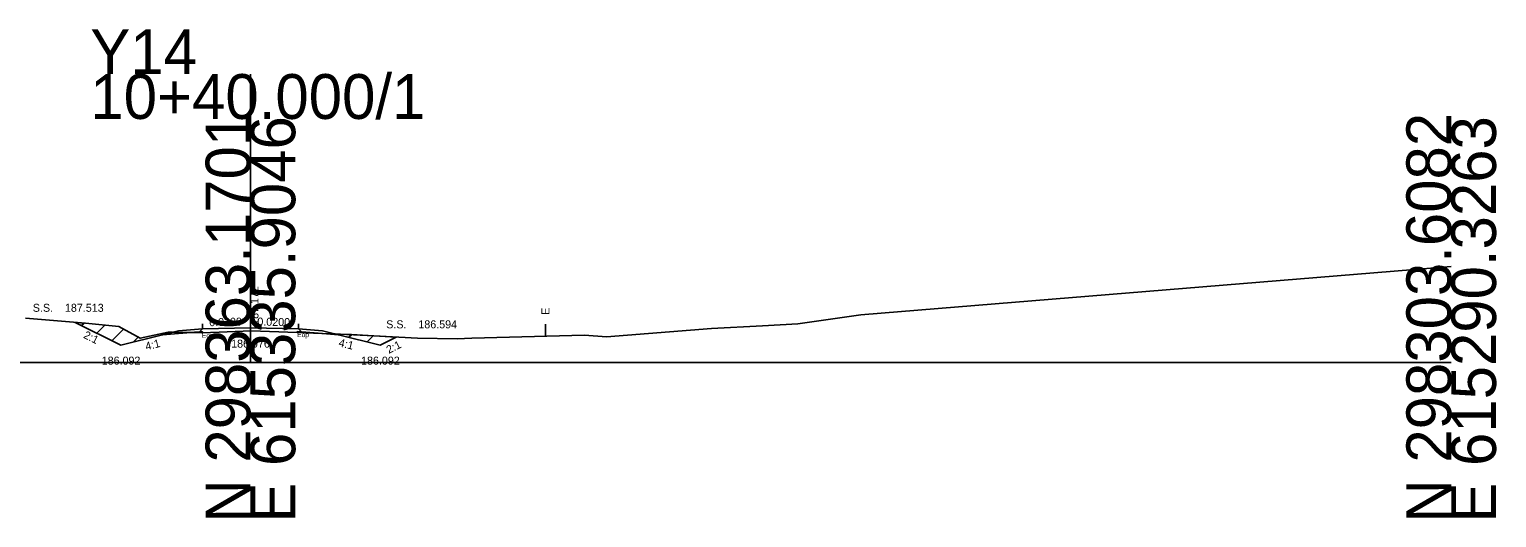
# Model space of a CAD drawing. Extents: x 517327 to 517505, y 114839 to 117370.
# Drawn here: x 517413.6 to 517505.2, y 115838.7 to 115869.2 of the extents above; entities that cross this region are included whole.
import ezdxf

# ---------------------------------------------------------------- set-up
doc = ezdxf.new("R2010")
doc.units = 0
for name, color, linetype in [('Exist XS Ground Line', 7, 'Continuous'), ('Old_Level_60', 7, 'Continuous'), ('Old_Level_63', 7, 'Continuous'), ('Prop XS Dump Level', 7, 'Continuous'), ('Prop XS Earthwork Shape', 7, 'Continuous'), ('Prop XS Elevation Labels', 7, 'Continuous'), ('Prop XS EOT Tick Mark', 7, 'Continuous'), ('Prop XS Exc Vertical Line 1', 7, 'Continuous'), ('Prop XS Finish Grade', 7, 'Continuous'), ('Prop XS Finish Grade Earthwork', 7, 'Continuous'), ('Prop XS Finish Grade Pavement', 7, 'Continuous'), ('Prop XS Hydro Elevations', 7, 'Continuous'), ('Prop XS Label Text', 7, 'Continuous'), ('Prop XS Pvmt Edge Slope', 7, 'Continuous'), ('Prop XS SE Text', 7, 'Continuous'), ('Prop XS Side Slope Text', 7, 'Continuous'), ('Prop XS Subgrade Earthwork', 7, 'Continuous'), ('Prop XS Suitable Common Exc Shape', 7, 'Continuous'), ('Scratch_Level_0', 7, 'Continuous')]:
    doc.layers.add(name, color=color, linetype=linetype)

msp = doc.modelspace()

# ---------------------------------------------------------------- linework, layer by layer
at = {"layer": 'Exist XS Ground Line'}
for p, q in [((517465.493, 115851.36), (517502.365, 115854.375)), ((517413.306, 115851.146), (517417.054, 115850.824)), ((517417.054, 115850.824), (517419.152, 115850.615)), ((517456.159, 115850.488), (517459.355, 115850.658)), ((517459.355, 115850.658), (517461.563, 115850.785)), ((517461.563, 115850.785), (517465.493, 115851.36)), ((517419.152, 115850.615), (517420.485, 115849.887)), ((517420.485, 115849.887), (517422.22, 115850.263)), ((517422.22, 115850.263), (517423.777, 115850.24)), ((517423.777, 115850.24), (517424.332, 115850.22)), ((517424.332, 115850.22), (517425.406, 115850.263)), ((517425.406, 115850.263), (517427.409, 115850.342)), ((517427.409, 115850.342), (517430.285, 115850.255)), ((517430.285, 115850.255), (517433.361, 115850.126)), ((517433.361, 115850.126), (517433.684, 115850.114)), ((517433.684, 115850.114), (517435.073, 115850.038)), ((517435.073, 115850.038), (517437.806, 115849.884)), ((517437.806, 115849.884), (517440.267, 115849.858)), ((517440.267, 115849.858), (517441.2, 115849.891)), ((517441.2, 115849.891), (517448.233, 115850.074)), ((517448.233, 115850.074), (517449.611, 115849.984)), ((517449.611, 115849.984), (517456.159, 115850.488))]:
    msp.add_line(p, q, dxfattribs=at)
at = {"layer": 'Old_Level_63'}
for p, q in [((517427.365, 115848.365), (517427.365, 115866.395)), ((517352.365, 115848.365), (517427.365, 115848.365)), ((517427.365, 115848.365), (517502.365, 115848.365))]:
    msp.add_line(p, q, dxfattribs=at)
at = {"layer": 'Prop XS Dump Level'}
for p, q in [((517424.365, 115850.477), (517427.365, 115850.537)), ((517427.365, 115850.537), (517430.365, 115850.477))]:
    msp.add_line(p, q, dxfattribs=at)
at = {"layer": 'Prop XS Earthwork Shape'}
for points in [[(517416.422, 115850.878), (517417.054, 115850.824), (517419.152, 115850.615), (517420.485, 115849.887), (517422.22, 115850.263), (517423.557, 115850.243), (517422.865, 115850.188), (517421.871, 115850.108), (517419.265, 115849.457)], [(517423.557, 115850.243), (517423.777, 115850.24), (517424.332, 115850.22), (517424.367, 115850.221), (517424.365, 115850.297), (517424.181, 115850.293)], [(517430.285, 115850.298), (517430.283, 115850.255), (517431.832, 115850.19), (517430.549, 115850.293), (517430.365, 115850.297)], [(517431.832, 115850.19), (517433.361, 115850.126), (517433.684, 115850.114), (517435.073, 115850.038), (517436.47, 115849.959), (517435.465, 115849.457), (517432.859, 115850.108), (517431.865, 115850.188)]]:
    msp.add_lwpolyline(points, close=True, dxfattribs=at)
at = {"layer": 'Prop XS EOT Tick Mark'}
for p, q in [((517424.365, 115850.782), (517424.365, 115850.477)), ((517430.365, 115850.477), (517430.365, 115850.782))]:
    msp.add_line(p, q, dxfattribs=at)
at = {"layer": 'Prop XS Exc Vertical Line 1'}
msp.add_line((517445.787, 115850.76), (517445.787, 115850.01), dxfattribs=at)
at = {"layer": 'Prop XS Finish Grade'}
for p, q in [((517421.871, 115850.108), (517422.865, 115850.357)), ((517422.865, 115850.357), (517424.365, 115850.477)), ((517430.365, 115850.477), (517431.865, 115850.357)), ((517431.865, 115850.357), (517432.859, 115850.108))]:
    msp.add_line(p, q, dxfattribs=at)
at = {"layer": 'Prop XS Finish Grade Earthwork'}
for p, q in [((517416.422, 115850.878), (517419.265, 115849.457)), ((517419.265, 115849.457), (517421.871, 115850.108)), ((517432.859, 115850.108), (517435.465, 115849.457)), ((517435.465, 115849.457), (517436.47, 115849.959))]:
    msp.add_line(p, q, dxfattribs=at)
at = {"layer": 'Prop XS Finish Grade Pavement'}
for p, q in [((517427.365, 115850.537), (517424.365, 115850.477)), ((517430.365, 115850.477), (517427.365, 115850.537))]:
    msp.add_line(p, q, dxfattribs=at)
at = {"layer": 'Prop XS Pvmt Edge Slope'}
for p, q in [((517424.181, 115850.293), (517424.365, 115850.477)), ((517430.365, 115850.477), (517430.549, 115850.293))]:
    msp.add_line(p, q, dxfattribs=at)
at = {"layer": 'Prop XS Subgrade Earthwork'}
for p, q in [((517421.871, 115850.108), (517422.865, 115850.188)), ((517422.865, 115850.188), (517424.181, 115850.293)), ((517424.181, 115850.293), (517424.365, 115850.297)), ((517424.367, 115850.221), (517424.365, 115850.297)), ((517430.285, 115850.298), (517430.283, 115850.255)), ((517430.285, 115850.298), (517430.365, 115850.297)), ((517430.365, 115850.297), (517430.549, 115850.293)), ((517430.549, 115850.293), (517431.865, 115850.188)), ((517431.865, 115850.188), (517432.859, 115850.108))]:
    msp.add_line(p, q, dxfattribs=at)
at = {"layer": 'Prop XS Suitable Common Exc Shape'}
for points in [[(517422.22, 115850.263), (517423.557, 115850.243), (517422.865, 115850.188), (517421.871, 115850.108), (517419.265, 115849.457), (517416.422, 115850.878), (517417.054, 115850.824), (517419.152, 115850.615), (517420.485, 115849.887)], [(517424.367, 115850.221), (517424.365, 115850.297), (517424.181, 115850.293), (517423.557, 115850.243), (517423.777, 115850.24), (517424.332, 115850.22)], [(517430.549, 115850.293), (517431.832, 115850.19), (517430.285, 115850.255), (517430.285, 115850.298), (517430.365, 115850.297)], [(517435.073, 115850.038), (517436.47, 115849.959), (517435.465, 115849.457), (517432.859, 115850.108), (517431.865, 115850.188), (517431.832, 115850.19), (517433.361, 115850.126), (517433.684, 115850.114)]]:
    msp.add_lwpolyline(points, close=True, dxfattribs=at)
at = {"layer": 'Scratch_Level_0'}
for p, q in [((517416.822, 115850.678), (517416.975, 115850.831)), ((517417.765, 115850.207), (517418.262, 115850.704)), ((517418.708, 115849.735), (517419.434, 115850.461)), ((517420.036, 115849.65), (517420.348, 115849.962)), ((517421.922, 115850.121), (517422.021, 115850.22)), ((517433.517, 115849.944), (517433.683, 115850.109)), ((517434.648, 115849.661), (517435.028, 115850.04)), ((517436.252, 115849.85), (517436.367, 115849.965))]:
    msp.add_line(p, q, dxfattribs=at)
for points in [[(517416.422, 115850.878), (517419.265, 115849.457), (517421.871, 115850.108), (517422.492, 115850.263), (517422.22, 115850.263), (517420.485, 115849.887), (517419.152, 115850.615), (517417.054, 115850.824)], [(517436.47, 115849.959), (517435.465, 115849.457), (517432.859, 115850.108), (517432.633, 115850.165), (517433.361, 115850.126), (517435.073, 115850.038)]]:
    msp.add_lwpolyline(points, close=True, dxfattribs=at)

# ---------------------------------------------------------------- texts
at = {"layer": 'Old_Level_60'}
msp.add_text('186.976', height=0.5, dxfattribs=at).set_placement((517426.159, 115849.299))
at = {"layer": 'Old_Level_63'}
for s, p in [('Y14', (517417.362, 115866.395)), ('10+40.000/1', (517417.365, 115863.595))]:
    msp.add_text(s, height=2.8, dxfattribs=at).set_placement(p)
for s, p in [('N 298363.1701', (517427.365, 115838.365)), ('E 615335.9046', (517430.165, 115838.364)), ('N 298303.6082', (517502.365, 115838.365)), ('E 615290.3263', (517505.165, 115838.365))]:
    msp.add_text(s, height=2.8, rotation=90, dxfattribs=at).set_placement(p)
at = {"layer": 'Prop XS Dump Level'}
for s, height, p in [('Case1', 0.0122, (517422.865, 115850.344)), ('Eop', 0.3, (517424.331, 115849.92)), ('Eop', 0.3, (517430.285, 115849.955)), ('Case1', 0.0122, (517431.865, 115850.344))]:
    msp.add_text(s, height=height, dxfattribs=at).set_placement(p)
at = {"layer": 'Prop XS Elevation Labels'}
msp.add_text(' 187.172', height=0.5, rotation=90, dxfattribs=at).set_placement((517427.865, 115850.537))
at = {"layer": 'Prop XS Exc Vertical Line 1'}
msp.add_text('E', height=0.5, rotation=90, dxfattribs=at).set_placement((517446.037, 115851.353))
at = {"layer": 'Prop XS Hydro Elevations'}
for s, p in [('S.S.    187.513', (517413.772, 115851.54)), ('S.S.    186.594', (517435.846, 115850.506))]:
    msp.add_text(s, height=0.5, dxfattribs=at).set_placement(p)
at = {"layer": 'Prop XS Label Text'}
for rotation, p in [(14.03624, (517420.863, 115849.125)), (345.96376, (517432.838, 115849.392))]:
    msp.add_text('4:1', height=0.5, rotation=rotation, dxfattribs=at).set_placement(p)
at = {"layer": 'Prop XS SE Text'}
for rotation, p in [(1.14576, (517424.792, 115850.638)), (358.85424, (517427.792, 115850.681))]:
    msp.add_text('0.0200', height=0.5, rotation=rotation, dxfattribs=at).set_placement(p)
at = {"layer": 'Prop XS Side Slope Text'}
for rotation, p in [(333.43495, (517416.893, 115849.926)), (26.56505, (517436.005, 115848.903))]:
    msp.add_text('2:1', height=0.5, rotation=rotation, dxfattribs=at).set_placement(p)
for p in [(517418.074, 115848.237), (517434.274, 115848.237)]:
    msp.add_text('186.092', height=0.5, dxfattribs=at).set_placement(p)

doc.saveas('drawing.dxf')
